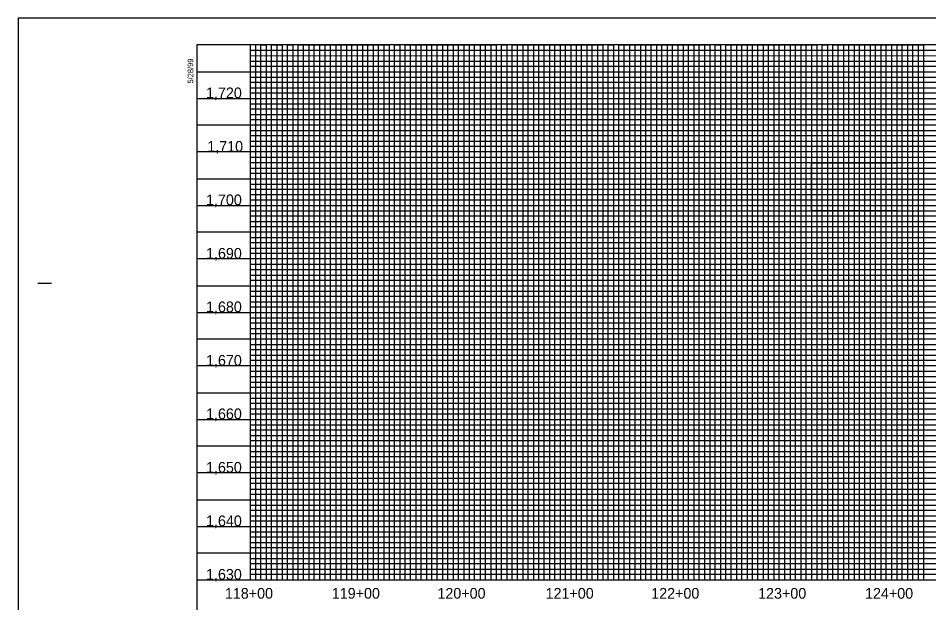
# Model space of a CAD drawing. Extents: x 505602 to 507286, y 483109 to 484209.
# Drawn here: x 505602 to 506454, y 483662 to 484209 of the extents above; entities that cross this region are included whole.
import ezdxf

# ---------------------------------------------------------------- set-up
doc = ezdxf.new("R2010")
doc.units = 0
for name, color, linetype in [('Exist Vertical Profile Vertical Axis Label', 7, 'Continuous'), ('Prop Grid Mask', 7, 'Continuous'), ('Sheet Layout Profile Border Port 1', 7, 'Continuous'), ('Sheet Plot Border Outside CELL', 7, 'Continuous'), ('Sheet Profile CELL', 7, 'Continuous'), ('Sheet Profile Grid Major CELL', 7, 'Continuous'), ('Sheet Profile Grid Middle CELL', 7, 'Continuous'), ('Sheet Profile Grid Minor CELL', 7, 'Continuous')]:
    doc.layers.add(name, color=color, linetype=linetype)

msp = doc.modelspace()

# ---------------------------------------------------------------- linework, layer by layer
at = {"layer": 'Prop Grid Mask'}
msp.add_lwpolyline([(506344.08, 484073.61), (506424.08, 484073.61), (506424.08, 484028.71), (506344.08, 484028.71)], close=True, dxfattribs=at)
at = {"layer": 'Sheet Layout Profile Border Port 1'}
msp.add_lwpolyline([(505819.08, 484183.71), (505819.08, 483683.71), (507219.08, 483683.71), (507219.08, 484022.66), (507069.03, 484022.66), (507069.03, 484183.71)], close=True, dxfattribs=at)
at = {"layer": 'Sheet Plot Border Outside CELL'}
msp.add_lwpolyline([(505602.08, 483108.71), (507286.08, 483108.71), (507286.08, 484208.71), (505602.08, 484208.71)], close=True, dxfattribs=at)
at = {"layer": 'Sheet Profile CELL'}
for p, q in [((505620.58, 483961.21), (505633.08, 483961.21)), ((505769.08, 483683.71), (507269.08, 483683.71))]:
    msp.add_line(p, q, dxfattribs=at)
msp.add_lwpolyline([(507269.08, 484183.71), (505769.08, 484183.71), (505769.08, 483133.71), (507269.08, 483133.71)], close=True, dxfattribs=at)
at = {"layer": 'Sheet Profile Grid Major CELL'}
for points in [[(505819.08, 484183.71), (505819.08, 483683.71), (505869.08, 483683.71), (505869.08, 484183.71), (505919.08, 484183.71), (505919.08, 483683.71), (505969.08, 483683.71), (505969.08, 484183.71), (506019.08, 484183.71), (506019.08, 483683.71), (506069.08, 483683.71), (506069.08, 484183.71), (506119.08, 484183.71), (506119.08, 483683.71), (506169.08, 483683.71), (506169.08, 484183.71), (506219.08, 484183.71), (506219.08, 483683.71), (506269.08, 483683.71), (506269.08, 484183.71), (506319.08, 484183.71), (506319.08, 483683.71), (506369.08, 483683.71), (506369.08, 484183.71), (506419.08, 484183.71), (506419.08, 483683.71), (506469.08, 483683.71)], [(505769.08, 484133.71), (507069.08, 484133.71)], [(507069.08, 484083.71), (505769.08, 484083.71), (505769.08, 484033.71), (507069.08, 484033.71)], [(507269.08, 483983.71), (505769.08, 483983.71), (505769.08, 483933.71), (507269.08, 483933.71)], [(507269.08, 483883.71), (505769.08, 483883.71), (505769.08, 483833.71), (507269.08, 483833.71)], [(507269.08, 483783.71), (505769.08, 483783.71), (505769.08, 483783.71), (505769.08, 483733.71), (507269.08, 483733.71)]]:
    msp.add_lwpolyline(points, dxfattribs=at)
at = {"layer": 'Sheet Profile Grid Middle CELL'}
msp.add_line((505769.08, 484158.71), (507069.03, 484158.71), dxfattribs=at)
for points in [[(505844.08, 484183.71), (505844.08, 483683.71), (505894.08, 483683.71), (505894.08, 484183.71), (505944.08, 484183.71), (505944.08, 483683.71), (505994.08, 483683.71), (505994.08, 484183.71), (506044.08, 484183.71), (506044.08, 483683.71), (506094.08, 483683.71), (506094.08, 484183.71), (506144.08, 484183.71), (506144.08, 483683.71), (506194.08, 483683.71), (506194.08, 484183.71), (506244.08, 484183.71), (506244.08, 483683.71), (506294.08, 483683.71), (506294.08, 484183.71), (506344.08, 484183.71), (506344.08, 483683.71), (506394.08, 483683.71), (506394.08, 483683.71), (506394.08, 484183.71), (506444.08, 484183.71), (506444.08, 483683.71), (506494.08, 483683.71)], [(507069.08, 484108.71), (505769.08, 484108.71), (505769.08, 484058.71), (507069.08, 484058.71)], [(507269.08, 484008.71), (505769.08, 484008.71), (505769.08, 483958.71), (507094.08, 483958.71)], [(507269.08, 483908.71), (505769.08, 483908.71), (505769.08, 483858.71), (507269.08, 483858.71)], [(507269.08, 483808.71), (505769.08, 483808.71), (505769.08, 483758.71), (507269.08, 483758.71)], [(507269.08, 483708.71), (505769.08, 483708.71)]]:
    msp.add_lwpolyline(points, dxfattribs=at)
at = {"layer": 'Sheet Profile Grid Minor CELL'}
for p, q in [((505819.08, 484178.71), (507069.08, 484178.71)), ((505819.08, 484173.71), (505819.08, 484173.71)), ((507069.08, 484173.71), (505819.08, 484173.36)), ((505819.08, 484168.71), (507069.08, 484168.71)), ((507069.03, 484048.71), (505819.08, 484048.71)), ((507069.08, 484043.71), (505819.08, 484043.71)), ((507069.08, 484038.71), (505819.08, 484038.71)), ((505819.08, 484028.71), (507069.08, 484028.71)), ((507069.08, 484023.71), (505819.08, 484023.71)), ((505819.08, 484018.71), (507219.08, 484018.71)), ((507219.08, 483998.71), (505819.08, 483998.71)), ((505819.08, 483993.71), (507219.08, 483993.71)), ((507219.08, 483973.71), (505819.08, 483973.71)), ((505819.08, 483968.71), (507219.08, 483968.71)), ((507219.08, 483948.71), (505819.08, 483948.71)), ((505819.08, 483943.71), (507219.08, 483943.71)), ((507219.08, 483938.71), (505819.08, 483938.71)), ((505819.08, 483928.71), (507219.08, 483928.71)), ((507219.08, 483923.71), (505819.08, 483923.71)), ((505819.08, 483918.71), (507219.08, 483918.71)), ((507219.08, 483913.71), (505819.08, 483913.71)), ((505819.08, 483903.71), (507219.08, 483903.71)), ((507219.08, 483898.71), (505819.08, 483898.71)), ((505819.08, 483893.71), (507219.08, 483893.71)), ((507219.08, 483888.71), (505819.08, 483888.71)), ((505819.08, 483878.71), (507219.08, 483878.71)), ((507219.08, 483873.71), (505819.08, 483873.71)), ((505819.08, 483868.71), (507219.08, 483868.71)), ((507219.08, 483863.71), (505819.08, 483863.71)), ((505819.08, 483853.71), (507219.08, 483853.71)), ((507219.08, 483848.71), (505819.08, 483848.71)), ((505819.08, 483843.71), (507219.08, 483843.71)), ((507219.08, 483838.71), (505819.08, 483838.71)), ((505819.08, 483828.71), (507219.08, 483828.71)), ((507219.08, 483823.71), (505819.08, 483823.71)), ((505819.08, 483818.71), (507219.08, 483818.71)), ((507219.08, 483813.71), (505819.08, 483813.71)), ((505819.08, 483803.71), (507219.08, 483803.71)), ((507219.08, 483798.71), (505819.08, 483798.71)), ((507219.08, 483793.71), (505819.08, 483793.71)), ((507219.08, 483788.71), (505819.08, 483788.71)), ((505819.08, 483778.71), (507219.08, 483778.71)), ((507219.08, 483773.71), (505819.08, 483773.71)), ((505819.08, 483768.71), (507219.08, 483768.71)), ((507219.08, 483763.71), (505819.08, 483763.71)), ((505819.08, 483753.71), (507219.08, 483753.71)), ((507219.08, 483748.71), (505819.08, 483748.71)), ((505819.08, 483743.71), (507219.08, 483743.71)), ((507219.08, 483738.71), (505819.08, 483738.71)), ((505819.08, 483728.71), (507219.08, 483728.71)), ((507219.08, 483723.71), (505819.08, 483723.71)), ((505819.08, 483718.71), (507219.08, 483718.71)), ((507219.08, 483713.71), (505819.08, 483713.71)), ((505819.08, 483703.71), (507219.08, 483703.71)), ((507219.08, 483698.71), (505819.08, 483698.71)), ((505819.08, 483693.71), (507219.08, 483693.71))]:
    msp.add_line(p, q, dxfattribs=at)
for points in [[(505824.08, 484183.71), (505824.08, 483683.71), (505829.08, 483683.71), (505829.08, 484183.71), (505834.08, 484183.71), (505834.08, 483683.71), (505839.08, 483683.71), (505839.08, 484183.71), (505849.08, 484183.71), (505849.08, 483683.71), (505854.08, 483683.71), (505854.08, 484183.71), (505859.08, 484183.71), (505859.08, 483683.71), (505864.08, 483683.71), (505874.08, 483683.71), (505879.08, 483683.71), (505879.08, 484183.71), (505884.08, 484183.71), (505884.08, 483683.71), (505889.08, 483683.71), (505889.08, 484183.71), (505899.08, 484183.71), (505899.08, 483683.71), (505904.08, 483683.71), (505904.08, 484183.71), (505909.08, 484183.71), (505909.08, 483683.71), (505914.08, 483683.71), (505914.08, 484183.71), (505924.08, 484183.71), (505924.08, 483683.71), (505929.08, 483683.71), (505929.08, 484183.71), (505934.08, 484183.71), (505934.08, 483683.71), (505939.08, 483683.71), (505939.08, 484183.71), (505949.08, 484183.71), (505949.08, 483683.71), (505954.08, 483683.71), (505954.08, 484183.71), (505959.08, 484183.71), (505959.08, 483683.71), (505964.08, 483683.71), (505964.08, 484183.71), (505974.08, 484183.71), (505974.08, 483683.71), (505979.08, 483683.71), (505979.08, 484183.71), (505984.08, 484183.71), (505984.08, 483683.71), (505989.08, 483683.71), (505989.08, 484183.71), (505999.08, 484183.71), (505999.08, 483683.71), (506004.08, 483683.71), (506004.08, 484183.71), (506009.08, 484183.71), (506009.08, 483683.71), (506014.08, 483683.71), (506014.08, 484183.71), (506024.08, 484183.71), (506024.08, 483683.71), (506029.08, 483683.71), (506029.08, 484183.71), (506034.08, 484183.71), (506034.08, 483683.71)], [(505864.08, 483683.71), (505864.08, 484183.71), (505874.08, 484183.71), (505874.08, 483683.71)], [(506034.08, 483683.71), (506039.08, 483683.71), (506039.08, 484183.71), (506049.08, 484183.71), (506049.08, 483683.71), (506054.08, 483683.71), (506054.08, 484183.71), (506059.08, 484183.71), (506059.08, 483683.71), (506064.08, 483683.71), (506064.08, 484183.71), (506074.08, 484183.71), (506074.08, 483683.71), (506079.08, 483683.71), (506079.08, 484183.71), (506084.08, 484183.71), (506084.08, 483683.71), (506089.08, 483683.71), (506089.08, 484183.71), (506099.08, 484183.71), (506099.08, 483683.71), (506104.08, 483683.71), (506104.08, 484183.71), (506109.08, 484183.71), (506109.08, 483683.71), (506114.08, 483683.71), (506114.08, 484183.71), (506124.08, 484183.71), (506124.08, 483683.71), (506129.08, 483683.71), (506129.08, 484183.71), (506134.08, 484183.71), (506134.08, 483683.71), (506139.08, 483683.71), (506139.08, 484183.71), (506149.08, 484183.71), (506149.08, 483683.71), (506154.08, 483683.71), (506154.08, 484183.71), (506159.08, 484183.71), (506159.08, 483683.71), (506164.08, 483683.71), (506164.08, 484183.71), (506174.08, 484183.71), (506174.08, 483683.71), (506179.08, 483683.71), (506179.08, 484183.71), (506184.08, 484183.71), (506184.08, 483683.71), (506189.08, 483683.71), (506189.08, 484183.71), (506199.08, 484183.71), (506199.08, 483683.71), (506204.08, 483683.71), (506204.08, 484183.71), (506209.08, 484183.71), (506209.08, 483683.71), (506214.08, 483683.71), (506214.08, 484183.71), (506224.08, 484183.71), (506224.08, 483683.71), (506229.08, 483683.71), (506229.08, 484183.71), (506234.08, 484183.71), (506234.08, 483683.71), (506239.08, 483683.71), (506239.08, 484183.71), (506249.08, 484183.71), (506249.08, 483683.71), (506254.08, 483683.71), (506254.08, 484183.71), (506259.08, 484183.71), (506259.08, 483683.71), (506264.08, 483683.71), (506264.08, 484183.71), (506274.08, 484183.71), (506274.08, 483683.71), (506279.08, 483683.71), (506279.08, 484183.71), (506284.08, 484183.71), (506284.08, 483683.71), (506289.08, 483683.71), (506289.08, 484183.71), (506299.08, 484183.71), (506299.08, 483683.71), (506304.08, 483683.71), (506304.08, 484183.71), (506309.08, 484183.71), (506309.08, 483683.71), (506314.08, 483683.71), (506314.08, 484183.71), (506324.08, 484183.71), (506324.08, 483683.71), (506329.08, 483683.71), (506329.08, 484183.71), (506334.08, 484183.71), (506334.08, 483683.71), (506339.08, 483683.71), (506339.08, 484183.71), (506349.08, 484183.71)], [(506349.08, 484183.71), (506349.08, 483683.71), (506354.08, 483683.71), (506354.08, 484183.71), (506359.08, 484183.71), (506359.08, 483683.71), (506364.08, 483683.71), (506364.08, 484183.71), (506374.08, 484183.71), (506374.08, 483683.71), (506379.08, 483683.71), (506379.08, 484183.71), (506384.08, 484183.71), (506384.08, 483683.71), (506389.08, 483683.71), (506389.08, 484183.71), (506399.08, 484183.71), (506399.08, 483683.71), (506404.08, 483683.71), (506404.08, 484183.71), (506409.08, 484183.71), (506409.08, 483683.71), (506414.08, 483683.71), (506414.08, 484183.71), (506424.08, 484183.71), (506424.08, 483683.71), (506429.08, 483683.71), (506429.08, 484183.71), (506434.08, 484183.71), (506434.08, 483683.71), (506439.08, 483683.71), (506439.08, 484183.71), (506449.08, 484183.71), (506449.08, 483683.71), (506454.08, 483683.71)], [(507069.08, 484163.71), (505819.08, 484163.71), (505819.08, 484153.71), (507069.08, 484153.71)], [(507069.03, 484148.71), (505819.08, 484148.71), (505819.08, 484143.71), (507069.08, 484143.71)], [(507069.08, 484138.71), (505819.08, 484138.71), (505819.08, 484128.71), (507069.08, 484128.71)], [(507069.08, 484123.71), (505819.08, 484123.71), (505819.08, 484118.71), (507069.08, 484118.71)], [(507069.08, 484113.71), (505819.08, 484113.71), (505819.08, 484103.71), (507069.08, 484103.71)], [(507069.08, 484098.71), (505819.08, 484098.71), (505819.08, 484093.71), (507069.08, 484093.71)], [(507069.08, 484088.71), (505819.08, 484088.71), (505819.08, 484078.71), (507069.08, 484078.71)], [(507069.08, 484073.61), (505819.18, 484073.61), (505819.18, 484068.71), (507069.08, 484068.71)], [(507069.08, 484063.71), (505819.08, 484063.71), (505819.08, 484053.71), (507069.08, 484053.71)], [(507219.08, 484013.71), (505819.08, 484013.71), (505819.08, 484003.71), (507219.08, 484003.71)], [(507219.08, 483988.71), (505819.08, 483988.71), (505819.08, 483978.71), (507219.08, 483978.71)], [(507219.08, 483963.71), (505819.08, 483963.71), (505819.08, 483953.71), (507219.08, 483953.71)], [(507219.08, 483688.71), (505819.08, 483688.71)]]:
    msp.add_lwpolyline(points, dxfattribs=at)

# ---------------------------------------------------------------- texts
at = {"layer": 'Exist Vertical Profile Vertical Axis Label'}
for s, p in [('1,720', (505777.78, 484133.96)), ('1,710', (505778.97, 484083.96)), ('1,700', (505777.78, 484033.96)), ('1,690', (505777.78, 483983.96)), ('1,680', (505777.78, 483933.96)), ('1,670', (505777.78, 483883.96)), ('1,660', (505777.78, 483833.96)), ('1,650', (505777.78, 483783.96)), ('1,640', (505777.78, 483733.96)), ('1,630', (505777.78, 483683.96)), ('118+00', (505795.45, 483666.21)), ('119+00', (505895.45, 483666.21)), ('120+00', (505994.26, 483666.21)), ('121+00', (506095.45, 483666.21)), ('122+00', (506194.26, 483666.21)), ('123+00', (506294.26, 483666.21)), ('124+00', (506394.26, 483666.21))]:
    msp.add_text(s, height=10, dxfattribs=at).set_placement(p)
at = {"layer": 'Sheet Profile CELL'}
msp.add_text('5/28/99', height=5.25, rotation=90, dxfattribs=at).set_placement((505765.84, 484147.62))

doc.saveas('drawing.dxf')
